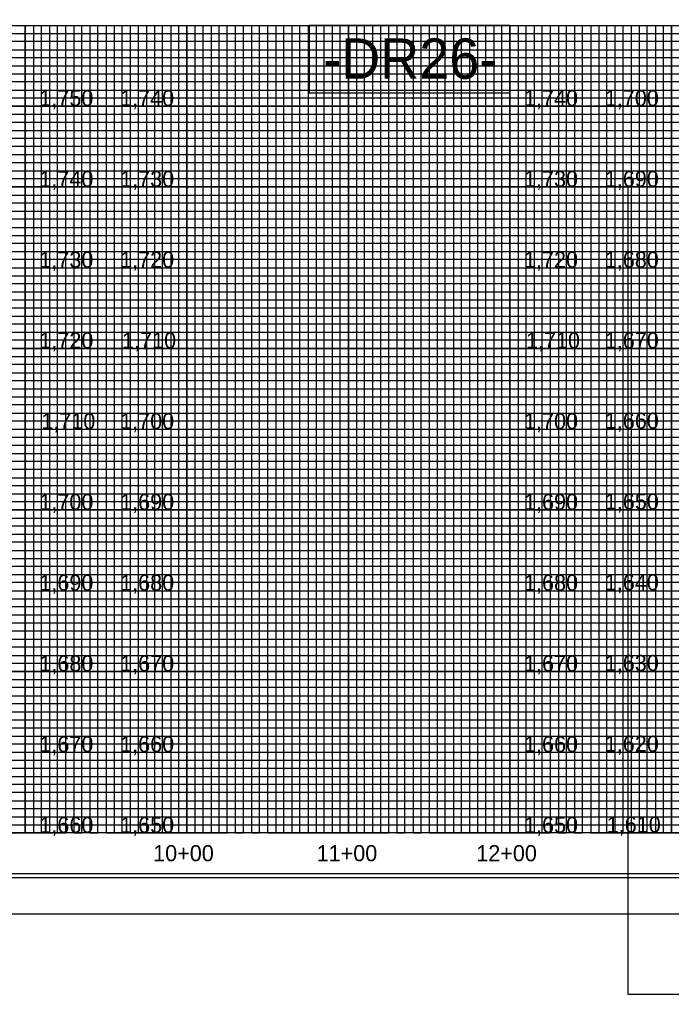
# Model space of a CAD drawing. Extents: x 505692 to 527456, y 415959 to 439886.
# Drawn here: x 506355 to 506759, y 438711 to 439315 of the extents above; entities that cross this region are included whole.
import ezdxf

# ---------------------------------------------------------------- set-up
doc = ezdxf.new("R2010")
doc.units = 0
for name, color, linetype in [('Exist Vertical Profile Vertical Axis Label', 7, 'Continuous'), ('Old_Level_1', 7, 'Continuous'), ('Prop Grid Mask', 7, 'Continuous'), ('Scratch_Level_4', 7, 'Continuous'), ('Sheet Cutting Line CELL', 7, 'Continuous'), ('Sheet DOT Grid CELL', 7, 'Continuous'), ('Sheet Layout Profile Border Port 2', 7, 'Continuous'), ('Sheet Plot Border Inside CELL', 7, 'Continuous'), ('Sheet Plot Border Outside CELL', 7, 'Continuous'), ('Sheet Profile CELL', 7, 'Continuous'), ('Sheet Profile Grid Major CELL', 7, 'Continuous'), ('Sheet Profile Grid Middle CELL', 7, 'Continuous'), ('Sheet Profile Grid Minor CELL', 7, 'Continuous')]:
    doc.layers.add(name, color=color, linetype=linetype)

msp = doc.modelspace()

# ---------------------------------------------------------------- linework, layer by layer
at = {"layer": 'Prop Grid Mask'}
msp.add_lwpolyline([(506658.68, 439311.14), (506534.38, 439311.14), (506534.38, 439269.44), (506658.68, 439269.44)], close=True, dxfattribs=at)
at = {"layer": 'Scratch_Level_4'}
msp.add_lwpolyline([(506758.68, 439311.14), (507008.68, 439311.14), (507008.68, 438811.14), (506758.68, 438811.14)], close=True, dxfattribs=at)
at = {"layer": 'Sheet Cutting Line CELL'}
msp.add_line((505691.68, 438761.14), (507375.68, 438761.14), dxfattribs=at)
at = {"layer": 'Sheet DOT Grid CELL'}
for p, q in [((505858.68, 439311.14), (507358.56, 439311.14)), ((506358.68, 439311.14), (506358.68, 438811.14)), ((506408.68, 439311.14), (506408.68, 438811.14)), ((506458.68, 439311.14), (506458.68, 438811.14)), ((506508.68, 439311.14), (506508.68, 438811.14)), ((506558.68, 439311.14), (506558.68, 438811.14)), ((506608.68, 439311.14), (506608.68, 438811.14)), ((506658.68, 439311.14), (506658.68, 438811.14)), ((506708.68, 439311.14), (506708.68, 438811.14)), ((506758.68, 439311.14), (506758.68, 438811.14)), ((505858.68, 439261.14), (507358.56, 439261.14)), ((505858.68, 439211.14), (507358.56, 439211.14)), ((505858.68, 439161.14), (507358.56, 439161.14)), ((505858.68, 439111.14), (507358.56, 439111.14)), ((505858.68, 439061.14), (507358.56, 439061.14)), ((505858.68, 439011.14), (507358.56, 439011.14)), ((505858.68, 438961.14), (507358.56, 438961.14)), ((505858.68, 438911.14), (507358.56, 438911.14)), ((505858.68, 438861.14), (507358.56, 438861.14))]:
    msp.add_line(p, q, dxfattribs=at)
at = {"layer": 'Sheet Layout Profile Border Port 2'}
for points in [[(505908.68, 439311.14), (506358.68, 439311.14), (506358.68, 438811.14), (505908.68, 438811.14)], [(506458.68, 439311.14), (506758.68, 439311.14), (506758.68, 438811.14), (506458.68, 438811.14)], [(506731.9, 439211.14), (507081.9, 439211.14), (507081.9, 438711.14), (506731.9, 438711.14)]]:
    msp.add_lwpolyline(points, close=True, dxfattribs=at)
at = {"layer": 'Sheet Plot Border Inside CELL'}
msp.add_lwpolyline([(505704.68, 438783.59), (507371.18, 438783.59), (507371.18, 439838.69), (505704.68, 439838.69)], close=True, dxfattribs=at)
at = {"layer": 'Sheet Plot Border Outside CELL'}
msp.add_lwpolyline([(505691.68, 438761.14), (507375.68, 438761.14), (507375.68, 439861.14), (505691.68, 439861.14)], close=True, dxfattribs=at)
at = {"layer": 'Sheet Profile CELL'}
for p, q in [((505858.68, 439311.14), (507358.68, 439311.14)), ((506408.68, 439311.14), (506408.68, 438811.14)), ((506708.68, 439311.14), (506708.68, 438811.14)), ((507358.68, 438811.14), (505858.68, 438811.14)), ((505858.68, 438786.14), (507358.68, 438786.14))]:
    msp.add_line(p, q, dxfattribs=at)
msp.add_lwpolyline([(507358.68, 439836.14), (505858.68, 439836.14), (505858.68, 438786.14), (507358.68, 438786.14)], close=True, dxfattribs=at)
at = {"layer": 'Sheet Profile Grid Major CELL'}
for p, q in [((506358.68, 439311.14), (506408.68, 439311.14)), ((506358.68, 439311.14), (506408.68, 439311.14)), ((506458.68, 439311.14), (506508.68, 439311.14)), ((506458.68, 439311.14), (506508.68, 439311.14)), ((506558.68, 439311.14), (506608.68, 439311.14)), ((506558.68, 439311.14), (506608.68, 439311.14)), ((506658.68, 439311.14), (506708.68, 439311.14)), ((506658.68, 439311.14), (506708.68, 439311.14)), ((506658.68, 439311.14), (506708.68, 439311.14)), ((506658.68, 439311.14), (506708.68, 439311.14))]:
    msp.add_line(p, q, dxfattribs=at)
for points in [[(506308.68, 438811.14), (506358.68, 438811.14), (506358.68, 439311.14), (506408.68, 439311.14), (506408.68, 438811.14), (506458.68, 438811.14), (506458.68, 439311.14), (506508.68, 439311.14), (506508.68, 438811.14), (506558.68, 438811.14), (506558.68, 439311.14), (506608.68, 439311.14), (506608.68, 438811.14), (506658.68, 438811.14), (506658.68, 439311.14), (506708.68, 439311.14), (506708.68, 438811.14), (506758.68, 438811.14), (506758.68, 439311.14), (506808.68, 439311.14)], [(507358.68, 439261.14), (505858.68, 439261.14)], [(507358.68, 439211.14), (505858.68, 439211.14), (505858.68, 439161.14), (507358.68, 439161.14)], [(507358.68, 439111.14), (505858.68, 439111.14), (505858.68, 439061.14), (507358.68, 439061.14)], [(507358.68, 439011.14), (505858.68, 439011.14), (505858.68, 438961.14), (507358.68, 438961.14)], [(507358.68, 438911.14), (505858.68, 438911.14), (505858.68, 438911.14), (505858.68, 438861.14), (507358.68, 438861.14)], [(507358.68, 438811.14), (505858.68, 438811.14)]]:
    msp.add_lwpolyline(points, dxfattribs=at)
at = {"layer": 'Sheet Profile Grid Middle CELL'}
for points in [[(506333.68, 438811.14), (506383.68, 438811.14), (506383.68, 439311.14), (506433.68, 439311.14), (506433.68, 438811.14), (506483.68, 438811.14), (506483.68, 438811.14), (506483.68, 439311.14), (506533.68, 439311.14), (506533.68, 438811.14), (506583.68, 438811.14), (506583.68, 439311.14), (506633.68, 439311.14), (506633.68, 438811.14), (506683.68, 438811.14), (506683.68, 439311.14), (506733.68, 439311.14), (506733.68, 438811.14), (506783.68, 438811.14)], [(505858.68, 439286.14), (507358.68, 439286.14)], [(507358.68, 439236.14), (505858.68, 439236.14), (505858.68, 439186.14), (507358.68, 439186.14)], [(507358.68, 439136.14), (505858.68, 439136.14), (505858.68, 439086.14), (507358.68, 439086.14)], [(507358.68, 439036.14), (505858.68, 439036.14), (505858.68, 438986.14), (507358.68, 438986.14)], [(507358.68, 438936.14), (505858.68, 438936.14), (505858.68, 438886.14), (507358.68, 438886.14)], [(507358.68, 438836.14), (505858.68, 438836.14)]]:
    msp.add_lwpolyline(points, dxfattribs=at)
at = {"layer": 'Sheet Profile Grid Minor CELL'}
for p, q in [((505908.68, 439306.14), (507308.68, 439306.14)), ((507308.68, 439301.14), (505908.68, 439301.14)), ((505908.68, 439296.14), (507308.68, 439296.14)), ((507308.68, 439291.14), (505908.68, 439291.14)), ((505908.68, 439281.14), (507308.68, 439281.14)), ((507308.68, 439276.14), (505908.68, 439276.14)), ((505908.68, 439271.14), (507308.68, 439271.14)), ((507308.68, 439266.14), (505908.68, 439266.14)), ((505908.68, 439256.14), (507308.68, 439256.14)), ((507308.68, 439251.14), (505908.68, 439251.14)), ((505908.68, 439246.14), (507308.68, 439246.14)), ((507308.68, 439241.14), (505908.68, 439241.14)), ((505908.68, 439231.14), (507308.68, 439231.14)), ((507308.68, 439226.14), (505908.68, 439226.14)), ((505908.68, 439221.14), (507308.68, 439221.14)), ((507308.68, 439216.14), (505908.68, 439216.14)), ((505908.68, 439206.14), (507308.68, 439206.14)), ((507308.68, 439201.14), (505908.68, 439201.14)), ((505908.68, 439196.14), (507308.68, 439196.14)), ((507308.68, 439191.14), (505908.68, 439191.14)), ((505908.68, 439181.14), (507308.68, 439181.14)), ((507308.68, 439176.14), (505908.68, 439176.14)), ((505908.68, 439171.14), (507308.68, 439171.14)), ((507308.68, 439166.14), (505908.68, 439166.14)), ((505908.68, 439156.14), (507308.68, 439156.14)), ((507308.68, 439151.14), (505908.68, 439151.14)), ((505908.68, 439146.14), (507308.68, 439146.14)), ((507308.68, 439141.14), (505908.68, 439141.14)), ((505908.68, 439131.14), (507308.68, 439131.14)), ((507308.68, 439126.14), (505908.68, 439126.14)), ((505908.68, 439121.14), (507308.68, 439121.14)), ((507308.68, 439116.14), (505908.68, 439116.29)), ((505908.68, 439106.14), (507308.68, 439106.14)), ((507308.68, 439101.14), (505908.68, 439101.14)), ((505908.68, 439096.14), (507308.68, 439096.14)), ((507308.68, 439091.14), (505908.68, 439091.14)), ((505908.68, 439081.14), (507308.68, 439081.14)), ((507308.68, 439076.14), (505908.68, 439076.14)), ((505908.68, 439071.14), (507308.68, 439071.14)), ((507308.68, 439066.14), (505908.68, 439066.14)), ((505908.68, 439056.14), (507308.68, 439056.14)), ((507308.68, 439051.14), (505908.68, 439051.14)), ((505908.68, 439046.14), (507308.68, 439046.14)), ((507308.68, 439041.14), (505908.68, 439041.14)), ((505908.68, 439031.14), (507308.68, 439031.14)), ((507308.68, 439026.14), (505908.68, 439026.14)), ((505908.68, 439021.14), (507308.68, 439021.14)), ((507308.68, 439016.14), (505908.68, 439016.14)), ((505908.68, 439006.14), (507308.68, 439006.14)), ((507308.68, 439001.14), (505908.68, 439001.14)), ((505908.68, 438996.14), (507308.68, 438996.14)), ((507308.68, 438991.14), (505908.68, 438991.14)), ((505908.68, 438981.14), (507308.68, 438981.14)), ((507308.68, 438976.14), (505908.68, 438976.14)), ((505908.68, 438971.14), (507308.68, 438971.14)), ((507308.68, 438966.14), (505908.68, 438966.14)), ((505908.68, 438956.14), (507308.68, 438956.14)), ((507308.68, 438951.14), (505908.68, 438951.14)), ((505908.68, 438946.14), (507308.68, 438946.14)), ((507308.68, 438941.14), (505908.68, 438941.14)), ((505908.68, 438931.14), (507308.68, 438931.14)), ((507308.68, 438926.14), (505908.68, 438926.14)), ((505908.68, 438921.14), (507308.68, 438921.14)), ((507308.68, 438916.14), (505908.68, 438916.14)), ((505908.68, 438906.14), (507308.68, 438906.14)), ((507308.68, 438901.14), (505908.68, 438901.14)), ((505908.68, 438896.14), (507308.68, 438896.14)), ((507308.68, 438891.14), (505908.68, 438891.14)), ((505908.68, 438881.14), (507308.68, 438881.14)), ((507308.68, 438876.14), (505908.68, 438876.14)), ((505908.68, 438871.14), (507308.68, 438871.14)), ((507308.68, 438866.14), (505908.68, 438866.14)), ((505908.68, 438856.14), (507308.68, 438856.14)), ((507308.68, 438851.14), (505908.68, 438851.14)), ((505908.68, 438846.14), (507308.68, 438846.14)), ((507308.68, 438841.14), (505908.68, 438841.14)), ((505908.68, 438831.14), (507308.68, 438831.14)), ((507308.68, 438826.14), (505908.68, 438826.14)), ((505908.68, 438821.14), (507308.68, 438821.14)), ((505908.68, 438816.14), (507308.68, 438816.14))]:
    msp.add_line(p, q, dxfattribs=at)
for points in [[(506353.68, 439311.14), (506363.68, 439311.14), (506363.68, 438811.14), (506368.68, 438811.14), (506368.68, 439311.14), (506373.68, 439311.14), (506373.68, 438811.14), (506378.68, 438811.14), (506378.68, 439311.14), (506388.68, 439311.14), (506388.68, 438811.14), (506393.68, 438811.14), (506393.68, 439311.14), (506398.68, 439311.14), (506398.68, 438811.14), (506403.68, 438811.14), (506403.68, 439311.14), (506413.68, 439311.14), (506413.68, 438811.14), (506418.68, 438811.14), (506418.68, 439311.14), (506423.68, 439311.14), (506423.68, 438811.14), (506428.68, 438811.14), (506428.68, 439311.14), (506438.68, 439311.14)], [(506438.68, 439311.14), (506438.68, 438811.14), (506443.68, 438811.14), (506443.68, 439311.14), (506448.68, 439311.14), (506448.68, 438811.14), (506453.68, 438811.14), (506453.68, 439311.14), (506463.68, 439311.14), (506463.68, 438811.14), (506468.68, 438811.14), (506468.68, 439311.14), (506473.68, 439311.14), (506473.68, 438811.14), (506478.68, 438811.14), (506478.68, 439311.14), (506488.68, 439311.14), (506488.68, 438811.14), (506493.68, 438811.14), (506493.68, 439311.14), (506498.68, 439311.14), (506498.68, 438811.14), (506503.68, 438811.14), (506503.68, 439311.14), (506513.68, 439311.14), (506513.68, 438811.14), (506518.68, 438811.14), (506518.68, 439311.14), (506523.68, 439311.14), (506523.68, 438811.14), (506528.68, 438811.14), (506528.68, 439311.14), (506538.68, 439311.14), (506538.68, 438811.14), (506543.68, 438811.14), (506543.68, 439311.14), (506548.68, 439311.14), (506548.68, 438811.14), (506553.68, 438811.14), (506553.68, 439311.14), (506563.68, 439311.14), (506563.68, 438811.14), (506563.68, 438811.14), (506568.68, 438811.14), (506568.68, 439311.14), (506573.68, 439311.14), (506573.68, 438811.14), (506578.68, 438811.14), (506578.68, 439311.14), (506588.68, 439311.14), (506588.68, 438811.14), (506593.68, 438811.14), (506593.68, 439311.14), (506598.68, 439311.14), (506598.68, 438811.14), (506603.68, 438811.14), (506603.68, 439311.14), (506613.68, 439311.14), (506613.68, 438811.14), (506618.68, 438811.14), (506618.68, 439311.14), (506623.68, 439311.14), (506623.68, 438811.14), (506628.68, 438811.14), (506628.68, 439311.14), (506638.68, 439311.14), (506638.68, 438811.14), (506643.68, 438811.14), (506643.68, 439311.14), (506648.68, 439311.14), (506648.68, 438811.14), (506653.68, 438811.14), (506653.68, 439311.14), (506663.68, 439311.14), (506663.68, 438811.14), (506668.68, 438811.14), (506668.68, 439311.14), (506673.68, 439311.14), (506673.68, 438811.14), (506678.68, 438811.14), (506678.68, 439311.14), (506688.68, 439311.14), (506688.68, 438811.14), (506693.68, 438811.14), (506693.68, 439311.14), (506698.68, 439311.14), (506698.68, 438811.14), (506703.68, 438811.14), (506703.68, 439311.14), (506713.68, 439311.14), (506713.68, 438811.14), (506718.38, 438811.69), (506718.68, 438811.14), (506718.68, 439311.14), (506723.68, 439311.14), (506723.68, 438811.14), (506728.68, 438811.14), (506728.68, 439311.14), (506738.68, 439311.14), (506738.68, 438811.14), (506743.68, 438811.14)], [(506743.68, 438811.14), (506743.68, 439311.14), (506748.68, 439311.14), (506748.68, 438811.14), (506753.68, 438811.14), (506753.68, 439311.14), (506763.68, 439311.14)]]:
    msp.add_lwpolyline(points, dxfattribs=at)

# ---------------------------------------------------------------- texts
at = {"layer": 'Exist Vertical Profile Vertical Axis Label'}
for s, p in [('1,750', (506367.37, 439261.14)), ('1,740', (506417.37, 439261.14)), ('1,740', (506667.37, 439261.14)), ('1,700', (506717.37, 439261.14)), ('1,740', (506367.37, 439211.14)), ('1,730', (506417.37, 439211.14)), ('1,730', (506667.37, 439211.14)), ('1,690', (506717.37, 439211.14)), ('1,730', (506367.37, 439161.14)), ('1,720', (506417.37, 439161.14)), ('1,720', (506667.37, 439161.14)), ('1,680', (506717.37, 439161.14)), ('1,720', (506367.37, 439111.14)), ('1,710', (506418.57, 439111.14)), ('1,710', (506668.57, 439111.14)), ('1,670', (506717.37, 439111.14)), ('1,710', (506368.57, 439061.14)), ('1,700', (506417.37, 439061.14)), ('1,700', (506667.37, 439061.14)), ('1,660', (506717.37, 439061.39)), ('1,700', (506367.37, 439011.14)), ('1,690', (506417.37, 439011.14)), ('1,690', (506667.37, 439011.14)), ('1,650', (506717.37, 439011.39)), ('1,690', (506367.37, 438961.14)), ('1,680', (506417.37, 438961.14)), ('1,680', (506667.37, 438961.14)), ('1,640', (506717.37, 438961.39)), ('1,680', (506367.37, 438911.14)), ('1,670', (506417.37, 438911.14)), ('1,670', (506667.37, 438911.14)), ('1,630', (506717.37, 438911.39)), ('1,670', (506367.37, 438861.14)), ('1,660', (506417.37, 438861.14)), ('1,660', (506667.37, 438861.14)), ('1,620', (506717.37, 438861.39)), ('1,660', (506367.37, 438811.14)), ('1,650', (506417.37, 438811.14)), ('1,650', (506667.37, 438811.14)), ('1,610', (506718.57, 438811.39)), ('10+00', (506437.81, 438793.64)), ('11+00', (506539, 438793.64)), ('12+00', (506637.81, 438793.64))]:
    msp.add_text(s, height=10, dxfattribs=at).set_placement(p)
at = {"layer": 'Old_Level_1'}
msp.add_text('-DR26-', height=25, dxfattribs=at).set_placement((506543.13, 439278.11))

doc.saveas('drawing.dxf')
